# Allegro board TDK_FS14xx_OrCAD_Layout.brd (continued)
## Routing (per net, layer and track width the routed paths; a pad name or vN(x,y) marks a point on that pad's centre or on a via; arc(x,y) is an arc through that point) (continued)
LED3: length 19.7
  TOP w0.229: U11.14 249.07,76.2 249.78,75.49 249.78,75.46 v2(251.21,74.04) 251.84,73.41 D3.1
  BOTTOM w0.305: U10.19 240.79,75.87 241.99,74.68 243.21,74.68 243.57,75.04 250.2,75.04 v2(251.21,74.04)
LED4: length 18.4
  TOP w0.229: D4.1 251.46,75.31 v2(251.21,75.56) 250.17,76.6 U11.15
  BOTTOM w0.305: U10.18 241.66,76.53 241.96,76.23 243.15,76.23 243.46,75.92 250.85,75.92 v2(251.21,75.56)
LED5: length 18.2
  TOP w0.229: U11.16 251.12,77 v2(251.21,77.09)
  TOP w0.305: D5.1 251.33,77.22 v2(251.21,77.09)
  BOTTOM w0.305: U10.17 240.93,77.18 241.48,77.72 243.36,77.72 244.4,76.68 250.8,76.68 v2(251.21,77.09)
LED6: length 19.1
  TOP w0.229: U11.17 249.99,77.4 v2(251.21,78.61)
  TOP w0.305: v2(251.21,78.61) 251.71,79.12 D6.1
  BOTTOM w0.305: v2(251.21,78.61) 250.57,79.25 241.76,79.25 241.3,78.79 241.3,78.36 240.77,77.83 U10.16
LED7: length 21.5
  TOP w0.229: v2(251.21,80.14) 250.62,79.55 248.62,79.55 247.41,78.35 U11.18
  TOP w0.305: v2(251.21,80.14) 252.09,81.03 D7.1
  BOTTOM w0.305: U10.15 240.25,78.48 241.27,79.5 241.27,80.31 241.73,80.77 250.57,80.77 v2(251.21,80.14)
LED8: length 23.8
  TOP w0.229: v2(251.21,81.66) 249.61,80.06 248.39,80.06 247.01,78.69 U11.19
  TOP w0.305: D8.1 252.48,82.93 v2(251.21,81.66)
  BOTTOM w0.305: U10.14 240.14,79.13 240.59,79.58 240.59,81.2 241.81,82.42 250.44,82.42 v2(251.21,81.66)
Net_107: length 1.2
  TOP w0.305: 200.6,52.97 200.6,53.71 v3(200.28,54.03)
Net_108: length 1.2
  TOP w0.305: 205.8,99.43 205.8,98.69 v3(206.12,98.37)
OPT: length 69.8
  TOP w0.305: R77.2 R76.1 271.59,32.57 271.3,32.87 267.82,32.87 J21.1 J20.2
  L3 w0.305: J13.6 273.08,82.55 273.86,81.76 273.86,38.91 J21.1
PGOOD1: length 244.5
  TOP w0.229: U11.10 247.41,74.13 244.14,70.87 v2(242.32,70.87)
  TOP w0.305: v2(242.32,70.87) 239.62,73.56 233.39,73.56 v2(230.7,70.87) ; v2(54.76,99.75) 53.87,100.63 53.01,100.63 52.87,100.77 U1.2
  L3 w0.305: v2(242.32,70.87) 245.14,68.05 263.42,68.05 J13.19 ; v2(230.7,70.87) 229.96,71.6 226.21,71.6 218.72,79.1 81,79.1 62.72,97.38 57.12,97.38 v2(54.76,99.75)
  BOTTOM w0.305: U10.3 232.37,73.92 232.03,73.58 232.03,72.19 v2(230.7,70.87) R56.1
PGOOD2: length 195.3
  TOP w0.229: v2(242.32,72.39) 245.01,72.39 247.01,74.4 U11.9
  TOP w0.305: v2(230.7,72.39) 232.45,74.14 240.56,74.14 v2(242.32,72.39) ; v2(105.38,100.05) 104.78,100.66 103.78,100.66 103.67,100.77 U2.2
  L3 w0.305: v2(105.38,100.05) 105.38,99.92 107.54,97.76 123.65,97.76 137.24,84.18 227.97,84.18 228.73,83.41 228.73,74.36 v2(230.7,72.39) ; v2(242.32,72.39) 245.87,68.83 265.18,68.83 J13.17
  BOTTOM w0.305: R57.1 v2(230.7,72.39) 231.44,73.13 231.44,73.81 232.21,74.57 U10.4
PGOOD3: length 140.9
  TOP w0.229: v2(242.32,73.91) 245.82,73.91 246.62,74.71 U11.8
  TOP w0.305: v2(242.32,73.91) 241.45,74.78 231.56,74.78 v2(230.7,73.91) ; v2(156.36,99.75) 155.4,100.71 154.53,100.71 154.47,100.77 U3.2
  L3 w0.305: v2(230.7,73.91) 229.31,75.3 229.31,84.86 225.5,88.67 184.15,88.67 175.23,97.59 158.52,97.59 v2(156.36,99.75) ; J13.15 265.81,70.74 255.22,70.74 254.2,71.75 244.47,71.75 v2(242.32,73.91)
  BOTTOM w0.305: R58.2 v2(230.7,73.91) 232.01,75.22 U10.5
PGOOD4: length 246.3
  TOP w0.229: U11.7 242.75,75 v2(242.32,75.44)
  TOP w0.305: U4.2 48.73,51.63 48.51,51.84 47.75,51.84 47.45,52.15 v2(47.45,52.63) ; v2(230.7,75.44) v2(242.32,75.44)
  L3 w0.305: v2(242.32,75.44) 244.45,73.3 253.24,73.3 254.03,72.52 266.57,72.52 J13.13 ; v2(47.45,52.63) 47.47,52.63 66.14,71.3 213.13,71.3 215.42,69.01 230.2,69.01 231.57,70.38 231.57,74.33 v2(230.7,75.44)
  BOTTOM w0.305: R59.1 v2(230.7,75.44) 231.14,75.87 U10.6
PGOOD5: length 198.6
  TOP w0.229: v2(242.32,76.96) 243.88,75.4 U11.6
  TOP w0.305: U5.2 99.53,51.63 99.26,51.89 98.5,51.89 98.25,52.15 v2(98.25,52.63) ; v2(230.7,76.96) v2(242.32,76.96)
  L3 w0.305: v2(242.32,76.96) 242.95,76.33 265.56,76.33 J13.9 ; v2(230.7,76.96) 232,76.96 232.56,76.4 232.56,69.24 228.98,65.66 210.13,65.66 209.32,66.47 112.17,66.47 98.32,52.63 v2(98.25,52.63)
  BOTTOM w0.305: R60.1 v2(230.7,76.96) 231.14,76.53 U10.7
PGOOD6: length 157
  TOP w0.229: v2(242.32,78.49) 243.31,77.5 243.31,77.24 244.75,75.8 U11.5
  TOP w0.305: U6.2 150.33,51.63 150.11,51.84 149.35,51.84 149.05,52.15 v2(149.05,52.63) ; v2(230.7,78.49) v2(242.32,78.49)
  L3 w0.305: v2(230.7,78.49) 233.71,78.49 235.71,76.48 235.71,66.62 230.66,61.57 207.92,61.57 207.52,61.98 158.47,61.98 149.12,52.63 v2(149.05,52.63) ; J13.7 252.78,80.01 252.17,79.4 243.23,79.4 v2(242.32,78.49)
  BOTTOM w0.305: U10.8 232.01,77.18 v2(230.7,78.49) R61.1
PGOOD7: length 107.7
  TOP w0.229: v2(242.32,80.01) 244.09,78.23 244.09,77.24 245.14,76.2 U11.4
  TOP w0.305: v2(195.53,103.12) 196.32,103.91 199.2,103.91 199.34,103.77 U7.9 ; v2(230.7,80.01) 231.28,80.59 241.73,80.59 v2(242.32,80.01)
  L3 w0.305: v2(195.53,103.12) 193.98,101.57 193.98,96.57 197.66,92.89 223.16,92.89 229.9,86.16 229.9,80.82 v2(230.7,80.01) ; J13.5 266.12,81.97 253.21,81.97 252.17,80.92 243.23,80.92 v2(242.32,80.01)
  BOTTOM w0.305: R62.2 v2(230.7,80.01) 231.47,79.24 231.47,78.61 232.26,77.83 U10.9
PGOOD8: length 117
  TOP w0.229: v2(242.32,81.53) 244.91,78.94 244.91,77.17 245.47,76.6 U11.3
  TOP w0.305: U8.9 206.77,48.63 207.14,48.26 v2(209.63,48.26) ; v2(230.7,81.53) v2(242.32,81.53)
  L3 w0.305: v2(242.32,81.53) 244.55,83.77 265.38,83.77 J13.3 ; v2(230.7,81.53) 231.34,80.9 235.28,80.9 237.24,78.94 238.68,78.94 239.73,77.9 239.73,66.09 232.18,58.55 215.34,58.55 212.39,55.6 v2(212.39,53.98)
  BOTTOM w0.305: R63.1 v2(230.7,81.53) 232.03,80.21 232.03,78.82 232.37,78.48 U10.10 ; v2(209.63,48.26) 210.36,48.26 212.39,50.29 v2(212.39,53.98)
SALERT7: length 13.5
  TOP w0.305: U7.14 198.45,100.15 197.84,99.54 191.24,99.54 J17.2
  BOTTOM w0.305: J17.2 190.12,98.42 R31.1
SALERT8: length 19.2
  TOP w0.305: U8.14 206.3,52.25 206.4,52.35 209.63,52.35 209.88,52.6 211.46,52.6 212.09,51.97 212.09,47.88 J14.2
  BOTTOM w0.305: R46.1 216.66,43.81 J14.2
SCL: length 492.5
  TOP w0.305: v2(194.87,100.36) 197.82,100.36 198.34,100.88 U7.13 ; U8.13 209.28,51.52 v2(209.32,51.56) ; v2(55.68,101.6) 53.54,101.6 53.27,101.87 U1.4 ; v2(106.55,101.6) 104.39,101.6 104.12,101.87 U2.4 ; J11.1 R48.1 ; v2(157.33,101.63) 155.14,101.63 154.89,101.87 U3.4 ; v2(94.59,50.16) 95.28,50.85 98.76,50.85 99.08,50.53 U5.4 ; U4.4 48.28,50.53 47.96,50.85 44.48,50.85 v2(43.79,50.16) ; v2(145.39,50.16) 146.08,50.85 149.56,50.85 149.88,50.53 U6.4
  L3 w0.305: v2(209.32,51.56) 211.12,49.76 224.84,49.76 239.88,34.72 245.49,34.72 264.46,15.75 J11.1 ; v2(198.3,77.09) v2(162.79,77.09) 162.74,77.14 v2(111.99,77.14) v2(60.63,77.14)
  BOTTOM w0.305: v2(55.68,101.6) 57.66,101.6 60.63,98.63 v2(60.63,77.14) 60.63,75.03 43.79,58.19 v2(43.79,50.16) ; v2(194.87,100.36) 193.68,99.16 193.68,81.71 v2(198.3,77.09) 209.32,66.07 v2(209.32,51.56) ; v2(157.33,101.63) 162.79,96.16 v2(162.79,77.09) 162.79,74.63 145.39,57.23 v2(145.39,50.16) ; v2(106.55,101.6) 111.99,96.16 v2(111.99,77.14) 111.99,75.06 94.59,57.66 v2(94.59,50.16)
SDA: length 483.7
  TOP w0.305: v2(155.09,99.77) 154.64,100.23 U3.1 ; U5.1 99.79,52.17 v2(99.36,52.6) ; v2(104.19,99.75) 103.71,100.23 U2.1 ; v2(210.97,51.59) 210.19,50.8 U8.12 ; J11.2 R47.1 ; v2(48.56,52.6) 48.99,52.17 U4.1 ; v2(150.16,52.6) 150.59,52.17 U6.1 ; v2(196.49,101.24) 196.85,101.6 U7.12 ; v2(53.34,99.75) 52.86,100.23 U1.1
  L3 w0.305: v2(144.07,52.6) 146.91,52.6 147.68,51.84 149.4,51.84 v2(150.16,52.6) ; v2(99.36,52.6) 98.6,51.84 96.88,51.84 96.11,52.6 v2(93.27,52.6) ; v2(42.47,52.6) 45.31,52.6 46.08,51.84 47.8,51.84 v2(48.56,52.6) ; v2(204.57,75.26) v2(158.27,75.26) v2(108.64,75.26) v2(57.58,75.26) ; v2(210.97,51.59) 226.06,51.59 237.26,40.39 246.38,40.39 J11.2
  BOTTOM w0.305: v2(93.27,52.6) 93.27,59.77 108.64,75.13 v2(108.64,75.26) 108.66,75.29 108.66,96.55 105.99,99.21 104.72,99.21 v2(104.19,99.75) ; v2(155.09,99.77) 155.85,99.01 157,99.01 158.27,97.74 v2(158.27,75.26) 144.07,61.06 v2(144.07,52.6) ; v2(196.49,101.24) 196.49,83.36 204.57,75.29 v2(204.57,75.26) 204.6,75.26 210.97,68.88 v2(210.97,51.59) ; v2(42.47,52.6) 42.47,60.15 v2(57.58,75.26) 57.58,99.39 56.26,100.71 54.31,100.71 v2(53.34,99.75)
SYNC7: length 13.4
  TOP w0.305: J17.1 191.48,102.32 U7.11
  BOTTOM w0.305: J17.1 190.12,100.97 R54.1
SYNC8: length 18.2
  TOP w0.305: U8.11 206.87,50.08 206.91,50.04 210.03,50.04 211.28,48.79 211.28,46.15 J14.1
  BOTTOM w0.305: J14.1 216.66,41.27 R38.1
VOUT1: length 112.7
  TOP w0.305: U1.5 53.73,102.43 v2(53.87,102.29)
  TOP w0.508: J2.1 50,139.23 C102.2
  TOP w0.813: 37.89,141.68 T3.1 ; T3.1 40.93,144.73 ; T3.1 37.89,144.73 ; T3.1 40.93,141.68 ; 42.89,134.67 T3.3 ; T3.3 45.93,137.72 ; T3.3 42.89,137.72 ; T3.3 45.93,134.67 ; T3.2 40.93,134.67 ; T3.2 40.93,137.72 ; T3.2 37.89,134.67 ; T3.2 37.89,137.72 ; T3.4 45.93,141.68 ; T3.4 42.89,141.68 ; T3.4 42.89,144.73 ; T3.4 45.93,144.73
  L3 w0.305: v2(51.41,106.91) 51.41,135.25 49.53,137.13 J2.1 ; v2(51.41,106.02) 51.41,104.75 v2(53.87,102.29)
  BOTTOM w0.813: T3.1 40.93,144.73 ; T3.1 37.89,144.73 ; T3.1 40.93,141.68 ; T3.1 37.89,141.68 ; 37.89,137.72 T3.2 ; T3.2 37.89,134.67 ; T3.2 40.93,137.72 ; T3.2 40.93,134.67 ; T3.3 45.93,134.67 ; T3.3 45.93,137.72 ; T3.3 42.89,137.72 ; T3.3 42.89,134.67 ; 42.89,144.73 T3.4 ; T3.4 45.93,144.73 ; T3.4 45.93,141.68 ; T3.4 42.89,141.68
  vias: v1(50.27,102.92) v1(50.8,102.93) v1(51.33,102.92) v2(49.38,106.91) v2(49.38,106.02) v2(50.39,106.91) v2(50.39,106.02)
VOUT2: length 112.7
  TOP w0.305: v2(104.67,102.29) 104.53,102.43 U2.5
  TOP w0.635: C103.2 100.8,139.23 J3.1
  TOP w0.813: 88.69,137.72 T5.2 ; T5.2 91.73,137.72 ; T5.2 88.69,134.67 ; T5.2 91.73,134.67 ; T5.3 96.73,137.72 ; T5.3 96.73,134.67 ; T5.3 93.69,137.72 ; T5.3 93.69,134.67 ; T5.4 96.73,144.73 ; T5.4 96.73,141.68 ; T5.4 93.69,141.68 ; T5.4 93.69,144.73 ; 88.69,141.68 T5.1 ; T5.1 91.73,144.73 ; T5.1 91.73,141.68 ; T5.1 88.69,144.73
  L3 w0.305: v2(104.67,102.29) 102.21,104.75 v2(102.21,106.02) ; J3.1 100.33,137.36 102.21,135.48 v2(102.21,106.91)
  BOTTOM w0.813: T5.1 91.73,141.68 ; T5.1 91.73,144.73 ; T5.1 88.69,141.68 ; T5.1 88.69,144.73 ; 93.69,137.72 T5.3 ; T5.3 96.73,137.72 ; T5.3 93.69,134.67 ; T5.3 96.73,134.67 ; T5.2 91.73,134.67 ; T5.2 91.73,137.72 ; T5.2 88.69,137.72 ; T5.2 88.69,134.67 ; T5.4 96.73,141.68 ; T5.4 93.69,144.73 ; T5.4 93.69,141.68 ; T5.4 96.73,144.73
  vias: v1(101.07,102.92) v1(101.6,102.93) v1(102.13,102.92) v2(100.18,106.91) v2(100.18,106.02) v2(101.19,106.91) v2(101.19,106.02)
VOUT3: length 112.7
  TOP w0.305: v2(155.47,102.29) 155.33,102.43 U3.5
  TOP w0.508: J4.1 151.6,139.23 C104.2
  TOP w0.813: T7.2 142.53,137.72 ; T7.2 139.49,134.67 ; T7.2 142.53,134.67 ; T7.2 139.49,137.72 ; 144.49,144.73 T7.4 ; T7.4 147.53,144.73 ; T7.4 147.53,141.68 ; T7.4 144.49,141.68 ; T7.3 147.53,137.72 ; T7.3 147.53,134.67 ; T7.3 144.49,137.72 ; T7.3 144.49,134.67 ; T7.1 142.53,141.68 ; T7.1 142.53,144.73 ; T7.1 139.49,144.73 ; T7.1 139.49,141.68
  L3 w0.305: v2(155.47,102.29) 153.01,104.75 v2(153.01,106.02) ; v2(153.01,106.91) 153.01,135.69 151.13,137.57 J4.1
  BOTTOM w0.813: 144.49,134.67 T7.3 ; T7.3 147.53,134.67 ; T7.3 144.49,137.72 ; T7.3 147.53,137.72 ; 139.49,137.72 T7.2 ; T7.2 142.53,134.67 ; T7.2 142.53,137.72 ; T7.2 139.49,134.67 ; 139.49,141.68 T7.1 ; T7.1 142.53,144.73 ; T7.1 142.53,141.68 ; T7.1 139.49,144.73 ; 144.49,141.68 T7.4 ; T7.4 147.53,141.68 ; T7.4 144.49,144.73 ; T7.4 147.53,144.73
  vias: v1(151.87,102.92) v1(152.4,102.93) v1(152.93,102.92) v2(150.98,106.91) v2(150.98,106.02) v2(151.99,106.91) v2(151.99,106.02)
VOUT4: length 112.2
  TOP w0.305: v2(47.73,50.11) 47.87,49.97 U4.5
  TOP w0.635: J5.1 49.53,15.79 C106.2
  TOP w0.813: 42.89,14.68 T9.4 ; T9.4 42.89,17.73 ; T9.4 45.93,17.73 ; T9.4 45.93,14.68 ; T9.2 40.93,7.67 ; T9.2 37.89,7.67 ; T9.2 40.93,10.72 ; T9.2 37.89,10.72 ; T9.1 40.93,17.73 ; T9.1 37.89,17.73 ; T9.1 40.93,14.68 ; T9.1 37.89,14.68 ; T9.3 45.93,10.72 ; T9.3 42.89,7.67 ; T9.3 42.89,10.72 ; T9.3 45.93,7.67
  L3 w0.305: v2(50.19,45.49) 50.19,16.13 49.53,15.47 J5.1 ; v2(47.73,50.11) 50.19,47.65 v2(50.19,46.38)
  BOTTOM w0.813: T9.3 45.93,10.72 ; T9.3 45.93,7.67 ; T9.3 42.89,7.67 ; T9.3 42.89,10.72 ; 37.89,10.72 T9.2 ; T9.2 37.89,7.67 ; T9.2 40.93,7.67 ; T9.2 40.93,10.72 ; 37.89,17.73 T9.1 ; T9.1 40.93,14.68 ; T9.1 37.89,14.68 ; T9.1 40.93,17.73 ; T9.4 45.93,17.73 ; T9.4 42.89,14.68 ; T9.4 45.93,14.68 ; T9.4 42.89,17.73
  vias: v1(50.27,49.48) v1(50.8,49.47) v1(51.33,49.48) v2(51.21,46.38) v2(51.21,45.49) v2(52.22,46.38) v2(52.22,45.49)
VOUT5: length 112.2
  TOP w0.305: v2(98.53,50.11) 98.67,49.97 U5.5
  TOP w0.508: J6.1 100.8,13.17 C105.2
  TOP w0.813: T11.3 96.73,7.67 ; T11.3 96.73,10.72 ; T11.3 93.69,7.67 ; T11.3 93.69,10.72 ; 93.69,14.68 T11.4 ; T11.4 96.73,14.68 ; T11.4 96.73,17.73 ; T11.4 93.69,17.73 ; T11.1 91.73,17.73 ; T11.1 91.73,14.68 ; T11.1 88.69,17.73 ; T11.1 88.69,14.68 ; 88.69,10.72 T11.2 ; T11.2 88.69,7.67 ; T11.2 91.73,7.67 ; T11.2 91.73,10.72
  L3 w0.305: v2(98.53,50.11) 100.99,47.65 v2(100.99,46.38) ; v2(100.99,45.49) 100.99,16.36 100.33,15.7 J6.1
  BOTTOM w0.813: 88.69,14.68 T11.1 ; T11.1 88.69,17.73 ; T11.1 91.73,14.68 ; T11.1 91.73,17.73 ; 93.69,7.67 T11.3 ; T11.3 96.73,10.72 ; T11.3 93.69,10.72 ; T11.3 96.73,7.67 ; T11.4 96.73,17.73 ; T11.4 96.73,14.68 ; T11.4 93.69,14.68 ; T11.4 93.69,17.73 ; T11.2 91.73,10.72 ; T11.2 91.73,7.67 ; T11.2 88.69,7.67 ; T11.2 88.69,10.72
  vias: v1(101.07,49.48) v1(101.6,49.47) v1(102.13,49.48) v2(102.01,46.38) v2(102.01,45.49) v2(103.02,46.38) v2(103.02,45.49)
VOUT6: length 112.2
  TOP w0.305: v2(149.33,50.11) 149.47,49.97 U6.5
  TOP w0.508: J7.1 151.6,13.17 C107.2
  TOP w0.813: 144.49,14.68 T13.4 ; T13.4 144.49,17.73 ; T13.4 147.53,17.73 ; T13.4 147.53,14.68 ; 139.49,14.68 T13.1 ; T13.1 142.53,17.73 ; T13.1 142.53,14.68 ; T13.1 139.49,17.73 ; T13.3 147.53,10.72 ; T13.3 144.49,10.72 ; T13.3 144.49,7.67 ; T13.3 147.53,7.67 ; 139.49,7.67 T13.2 ; T13.2 142.53,10.72 ; T13.2 142.53,7.67 ; T13.2 139.49,10.72
  L3 w0.305: J7.1 151.13,15.7 151.79,16.36 v2(151.79,45.49) ; v2(149.33,50.11) 151.79,47.65 v2(151.79,46.38)
  BOTTOM w0.813: T13.3 147.53,10.72 ; T13.3 147.53,7.67 ; T13.3 144.49,10.72 ; T13.3 144.49,7.67 ; T13.1 142.53,17.73 ; T13.1 142.53,14.68 ; T13.1 139.49,14.68 ; T13.1 139.49,17.73 ; T13.4 147.53,14.68 ; T13.4 144.49,14.68 ; T13.4 147.53,17.73 ; T13.4 144.49,17.73 ; T13.2 142.53,10.72 ; T13.2 139.49,10.72 ; T13.2 142.53,7.67 ; T13.2 139.49,7.67
  vias: v1(151.87,49.48) v1(152.4,49.47) v1(152.93,49.48) v2(152.81,46.38) v2(152.81,45.49) v2(153.82,46.38) v2(153.82,45.49)
VOUT7: length 110.4
  TOP w0.508: C108.2 204,139.23 J9.1
  TOP w0.813: T15.1 211.11,141.68 ; T15.1 208.07,141.68 ; T15.1 208.07,144.73 ; T15.1 211.11,144.73 ; 213.07,144.73 T15.4 ; T15.4 216.11,144.73 ; T15.4 213.07,141.68 ; T15.4 216.11,141.68 ; T15.3 216.11,137.72 ; T15.3 216.11,134.67 ; T15.3 213.07,134.67 ; T15.3 213.07,137.72 ; T15.2 211.11,137.72 ; T15.2 208.07,134.67 ; T15.2 208.07,137.72 ; T15.2 211.11,134.67
  L3 w0.305: v2(204.34,106.27) 204.37,106.3 204.9,106.3 ; J9.1 205.41,138.76 205.41,106.81 204.9,106.3 ; 204.9,106.3 v2(206.35,106.3)
  BOTTOM w0.305: v2(206.35,106.3) R42.1 C51.1
  BOTTOM w0.813: T15.1 211.11,144.73 ; T15.1 208.07,144.73 ; T15.1 211.11,141.68 ; T15.1 208.07,141.68 ; T15.2 211.11,134.67 ; T15.2 211.11,137.72 ; T15.2 208.07,134.67 ; T15.2 208.07,137.72 ; 213.07,141.68 T15.4 ; T15.4 216.11,141.68 ; T15.4 216.11,144.73 ; T15.4 213.07,144.73 ; 213.07,134.67 T15.3 ; T15.3 213.07,137.72 ; T15.3 216.11,137.72 ; T15.3 216.11,134.67
  vias: v1(201.8,103.78) v1(202.03,103.45) v1(202.26,103.78) v1(202.49,103.45) v1(202.72,103.78) v1(202.95,103.45) v1(203.17,103.78) v1(203.4,103.45) v1(203.63,103.78) v1(203.86,103.45) v1(204.09,103.78) v1(204.32,103.45) v1(204.55,103.78) v1(204.77,103.45) v2(203.45,109.83) v2(203.45,108.94) v2(203.45,108.05) v2(203.45,107.16) v2(203.45,106.27) v2(203.45,105.38) v2(204.34,109.83) v2(204.34,108.94) v2(204.34,108.05) v2(204.34,107.16) v2(204.34,105.38)
VOUT8: length 110.5
  TOP w0.508: C109.2 202.4,13.17 J8.1
  TOP w0.813: T17.2 193.33,7.67 ; T17.2 190.29,7.67 ; T17.2 193.33,10.72 ; T17.2 190.29,10.72 ; T17.1 193.33,14.68 ; T17.1 190.29,14.68 ; T17.1 193.33,17.73 ; T17.1 190.29,17.73 ; 195.29,17.73 T17.4 ; T17.4 198.33,17.73 ; T17.4 195.29,14.68 ; T17.4 198.33,14.68 ; T17.3 198.33,10.72 ; T17.3 195.29,7.67 ; T17.3 198.33,7.67 ; T17.3 195.29,10.72
  L3 w0.305: J8.1 201.29,13.34 201.29,45.01 v2(200.2,46.1) 202.03,46.1 v2(202.06,46.13)
  BOTTOM w0.305: v2(200.2,46.1) R52.1 C121.1
  BOTTOM w0.813: 190.29,7.67 T17.2 ; T17.2 193.33,10.72 ; T17.2 190.29,10.72 ; T17.2 193.33,7.67 ; 190.29,14.68 T17.1 ; T17.1 193.33,14.68 ; T17.1 190.29,17.73 ; T17.1 193.33,17.73 ; T17.3 198.33,10.72 ; T17.3 195.29,10.72 ; T17.3 195.29,7.67 ; T17.3 198.33,7.67 ; 195.29,17.73 T17.4 ; T17.4 198.33,14.68 ; T17.4 195.29,14.68 ; T17.4 198.33,17.73
  vias: v1(201.63,48.95) v1(201.85,48.62) v1(202.08,48.95) v1(202.31,48.62) v1(202.54,48.95) v1(202.77,48.62) v1(203,48.95) v1(203.23,48.62) v1(203.45,48.95) v1(203.68,48.62) v1(203.91,48.95) v1(204.14,48.62) v1(204.37,48.95) v1(204.6,48.62) v2(202.06,47.02) v2(202.06,45.24) v2(202.06,44.35) v2(202.06,43.46) v2(202.06,42.57) v2(202.95,47.02) v2(202.95,46.13) v2(202.95,45.24) v2(202.95,44.35) v2(202.95,43.46) v2(202.95,42.57)
N106541: length 3.6
  TOP w0.305: C9.2 98.59,100.89 v1(99.14,100.89) 99.57,101.33 U2.11
  BOTTOM w0.305: R4.1 99.12,100.87 v1(99.14,100.89)
N109036: length 1.9
  TOP w0.305: U2.10 v1(99.06,101.87)
  BOTTOM w0.305: v1(99.06,101.87) 99.28,101.66 C132.2
N111800: length 3.6
  TOP w0.305: U3.11 150.37,101.33 v1(149.94,100.89) 149.39,100.89 C15.2
  BOTTOM w0.305: v1(149.94,100.89) 149.92,100.87 R7.1
N112773: length 3.6
  TOP w0.305: C3.2 47.79,100.89 v1(48.34,100.89) 48.77,101.33 U1.11
  BOTTOM w0.305: R1.1 48.32,100.87 v1(48.34,100.89)
N113813: length 3.6
  TOP w0.305: C21.2 53.81,51.51 v1(53.26,51.51) 52.83,51.07 U4.11
  BOTTOM w0.305: v1(53.26,51.51) 53.28,51.53 R10.1
N124020: length 1
  TOP w0.305: R6.2 103.54,102.97 U2.6
N125365: length 1
  TOP w0.305: R3.2 52.74,102.97 U1.6
N125599: length 1
  TOP w0.305: R12.2 48.86,49.43 U4.6
N125833: length 1
  TOP w0.305: U3.6 154.34,102.97 R9.2
N143732: length 3.6
  TOP w0.305: C29.2 104.61,51.51 v1(104.06,51.51) 103.63,51.07 U5.11
  BOTTOM w0.305: v1(104.06,51.51) 104.08,51.53 R21.1
N143740: length 3.6
  TOP w0.305: U6.11 154.43,51.07 v1(154.86,51.51) 155.41,51.51 C30.2
  BOTTOM w0.305: v1(154.86,51.51) 154.88,51.53 R22.1
N143880: length 1
  TOP w0.305: R23.2 99.66,49.43 U5.6
N143888: length 1
  TOP w0.305: R24.2 150.46,49.43 U6.6
N983153:
  vias: v1(203,99.19) v1(203.17,99.39) v1(203.4,99.19)
N983255:
  vias: v1(198.63,99.16) v1(198.63,98.65) v1(198.63,98.15) v1(199.14,99.16) v1(199.14,98.65) v1(199.14,98.15)
N983335: length 3.9
  TOP w0.305: R27.2 207.59,98.66 C43.2 207.61,98.82 206.28,100.15 U7.2
N983701: length 3.2
  TOP w0.305: v2(207.32,100.9) C45.2 U7.4
  BOTTOM w0.305: v2(207.32,100.9) 206.76,100.9 R36.2
N983781: length 4.5
  TOP w0.305: U7.5 207.63,102.32 207.77,102.46 v2(207.77,102.51) C44.2
  BOTTOM w0.305: R36.1 206.72,102.05 207.01,102.34 207.59,102.34 v2(207.77,102.51)
N983905: length 2.1
  TOP w0.305: R39.1 199.97,103.12 200.05,103.05 U7.10
N983923: length 6.4
  TOP w0.305: U7.6 206.68,103.05 v2(206.74,103.11)
  BOTTOM w0.305: R42.2 C51.2 208.49,105.28 208.69,105.08 208.69,103.66 208.47,103.44 R44.2 207.07,103.44 v2(206.74,103.11)
N1133327:
  vias: v1(203,53.21) v1(203.23,53.01) v1(203.4,53.21)
N1133411:
  vias: v1(207.26,54.25) v1(207.26,53.75) v1(207.26,53.24) v1(207.77,54.25) v1(207.77,53.75) v1(207.77,53.24)
N1133439: length 3.9
  TOP w0.305: R45.2 198.81,53.74 C115.2 198.79,53.58 200.12,52.25 U8.2
N1133683: length 3.2
  TOP w0.305: v2(199.08,51.5) C116.2 U8.4
  BOTTOM w0.305: R50.2 199.64,51.5 v2(199.08,51.5)
N1133735: length 4.5
  TOP w0.305: C117.2 v2(198.63,49.89) 198.63,49.94 198.77,50.08 U8.5
  BOTTOM w0.305: R50.1 199.61,50.06 198.81,50.06 v2(198.63,49.89)
N1133791: length 2.1
  TOP w0.305: U8.10 206.35,49.35 206.43,49.28 R51.1
N1133799: length 6.5
  TOP w0.305: U8.6 199.72,49.35 v2(199.66,49.29)
  BOTTOM w0.305: v2(199.66,49.29) 199.33,48.96 R53.2 197.86,48.96 197.64,48.75 197.64,47.34 197.86,47.12 C121.2 R52.2
N1144589: length 53.4
  TOP w0.305: SW3.10 275.64,99.57 ; 275.64,99.57 275.95,99.26 275.95,97.28 275.69,97.03 SW3.9 ; 275.64,99.57 275.82,99.75 275.82,101.68 275.39,102.11 ; 275.34,104.65 275.84,104.14 275.84,102.57 275.39,102.11 ; 275.34,104.65 SW3.12 ; 275.34,104.65 275.84,105.16 275.84,106.76 275.41,107.19 ; SW3.15 275.51,112.27 ; 275.51,112.27 275.84,111.94 275.84,110.34 275.23,109.73 ; 275.51,112.27 275.69,112.45 275.69,114.25 275.13,114.81 SW3.16 272.95,114.81 269.62,118.14 269.62,128.78 SW1.2 ; 275.39,102.11 SW3.11 ; SW3.13 275.41,107.19 ; 275.41,107.19 275.82,107.59 275.82,109.14 275.23,109.73 ; SW3.14 275.23,109.73
N1166950: length 4.7
  TOP w0.305: R75.1 267.08,52.7 267.33,52.96
N1167645: length 4.7
  TOP w0.305: R55.1 262.96,43.56 SW2.1
N1170426: length 3.8
  BOTTOM w0.305: R64.1 234.95,72.82 234.5,73.27 U10.2
N1170926: length 1.9
  TOP w0.305: D4.2 R69.2
N1170982: length 1.9
  TOP w0.305: D5.2 R70.2
N1171050: length 1.9
  TOP w0.305: D6.2 R71.2
N1171118: length 1.9
  TOP w0.305: D7.2 R72.2
N1171178: length 1.9
  TOP w0.305: R73.2 D8.2
N1171210: length 5.5
  BOTTOM w0.305: R65.2 236.22,73.19 236.96,73.92 U10.22
N1176310: length 1.9
  TOP w0.305: D3.2 R68.2
N1183669: length 1.9
  TOP w0.305: D1.2 R66.2
N1183969: length 1.9
  TOP w0.305: D2.2 R67.2
N1197737: length 5.3
  TOP w0.305: R74.1 SW1.1
N1197747: length 5.3
  TOP w0.305: R18.1 SW1.3
N1234759: length 1.9
  TOP w0.305: U1.10 v1(48.26,101.87)
  BOTTOM w0.305: C134.2 48.48,101.66 v1(48.26,101.87)
N1235035: length 1.9
  TOP w0.305: U4.10 v1(53.34,50.53)
  BOTTOM w0.305: v1(53.34,50.53) 53.12,50.74 C135.2
N1235784: length 1.9
  TOP w0.305: U6.10 v1(154.94,50.53)
  BOTTOM w0.305: v1(154.94,50.53) 154.72,50.74 C136.2
N1236304: length 1.9
  TOP w0.305: U5.10 v1(104.14,50.53)
  BOTTOM w0.305: v1(104.14,50.53) 103.92,50.74 C137.2
N1413705: length 6.5
  TOP w0.305: J19.2 J20.1 R78.2 R77.1

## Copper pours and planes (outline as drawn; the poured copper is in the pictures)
3.3V on TOP: 267.92,89.92 267.92,85.5 265.1,85.5 265.1,55.68 260.88,55.68 260.88,45.21 262.1,45.21 262.1,27.3 271.27,27.3 271.27,28.98 272.72,28.98 272.72,23.29 257.07,23.29 256.97,23.39 256.97,45.44 256.95,45.47 241.35,45.47 241.35,60.15 224.54,60.15 224.54,83.64 243.59,83.64 246.94,80.29 246.94,78.77 246.15,77.98 245.41,77.98 245.29,78.11 245.29,79.55 243.03,81.81 229.51,81.81 229.51,70 231.29,70 234.29,73 238.56,73 243.15,68.4 259.49,68.4 259.49,89.92
3.3V on BOTTOM: 239.78,53.16 244.53,53.16 244.53,46.05 240.97,46.05 240.97,51.03 239.78,51.03
AGND1 on BOTTOM: 205.18,102.11 205.18,102.67 203.2,102.67 203.2,102.11
AGND1 on L2: 203.12,102.95 203.12,102.03 205.21,102.03 205.21,102.95
AGND1 on L3: 203.12,102.03 205.94,102.03 207.44,103.53 211.66,103.53 211.76,103.63 211.76,111.23 184.58,111.23 184.56,111.2 184.56,96.7 187.38,93.88 192.63,93.88 192.63,102.82 193.73,103.91 196.24,103.91 196.24,102.62 197.61,102.62 197.61,103.45 202.97,103.45 203.12,103.3
AGND2 on BOTTOM: 201.22,50.29 201.22,49.73 203.2,49.73 203.2,50.29
AGND2 on L2: 201.32,49.45 203.33,49.45 203.33,50.42 201.32,50.42
AGND2 on L3: 203.28,50.37 200.46,50.37 198.96,48.87 194.74,48.87 194.64,48.77 194.64,41.17 209.12,41.17 210.13,40.16 221.21,40.16 221.46,40.41 221.46,46.3 219.84,47.93 211.84,47.93 209.88,49.89 206.63,49.89 205.69,48.95 203.43,48.95 203.28,49.1
PGND on TOP (solid shape): 51.07,50.75 51.67,50.75 51.67,49.95 49.93,49.95 49.93,51.75 51.07,51.75
PGND on TOP (solid shape): 51.67,100.65 50.53,100.65 50.53,101.65 49.93,101.65 49.93,102.45 51.67,102.45
PGND on TOP (solid shape): 101.87,50.75 102.47,50.75 102.47,49.95 100.73,49.95 100.73,51.75 101.87,51.75
PGND on TOP (solid shape): 102.47,100.65 101.33,100.65 101.33,101.65 100.73,101.65 100.73,102.45 102.47,102.45
PGND on TOP (solid shape): 152.67,50.75 153.27,50.75 153.27,49.95 151.53,49.95 151.53,51.75 152.67,51.75
PGND on TOP (solid shape): 153.27,100.65 152.13,100.65 152.13,101.65 151.53,101.65 151.53,102.45 153.27,102.45
PGND on TOP (solid shape): outline of 651 points within 101.96,93.07 151.28,151.08
PGND on TOP (solid shape): outline of 1438 points within 1.37,1.3 49.68,151.05
PGND on TOP: 276.63,70.92 278.08,70.92 278.08,1.32 203.61,1.32 203.61,24 205.69,24 205.69,47.47 209.14,47.47 209.14,55.12 206.86,55.12 205.03,53.29 205.03,49.5 203.91,49.5 203.91,50.88 202.74,50.88 202.74,52.43 203.96,52.43 203.96,53.82 203.66,53.82 203.66,59.33 216.97,59.33 216.97,54.86 229.46,54.86 229.46,44.55 236.91,44.55 236.91,59.11 240.39,59.11 240.39,44.55 256.06,44.55 256.06,22.15 273.43,22.15 273.43,29.74 262.97,29.74 262.97,46.51 261.7,46.51 261.7,54.41 266.65,54.41 266.65,63.5 266.67,63.53 269.24,63.53 ; 3 cut-outs
PGND on TOP: 104.57,59.33 151.21,59.33 151.21,53.19 150.93,53.19 150.93,44.15 127.97,44.15 127.97,44.12 126.49,44.12 126.49,1.35 101.93,1.35 101.93,24.38 104.34,24.38 104.34,48.56 103.66,49.25 102.72,49.25 102.72,50.16 104.39,50.16 104.72,49.83 105.84,49.83 105.84,51.61 105.82,51.64 104.93,51.64 104.78,51.79 104.78,53.04 104.57,53.24
PGND on TOP: 152.76,151.08 202.82,151.08 202.82,128.07 200.71,128.07 200.71,104.93 197.31,104.93 197.31,97.1 199.36,97.1 201.37,99.11 201.37,102.9 202.49,102.9 202.49,101.52 203.66,101.52 203.66,99.97 202.44,99.97 202.44,98.58 202.87,98.58 202.87,93.07 153.59,93.07 153.59,99.21 155.04,99.21 155.91,100.08 155.91,101.9 155.88,101.93 155.88,103.89 154,103.89 154,127.99 152.76,127.99 ; 1 cut-out
PGND on TOP: 51.16,151.08 75.84,151.08 75.84,108.86 98.73,108.86 98.73,103.96 99.54,103.15 100.48,103.15 100.48,102.23 98.81,102.23 98.48,102.57 97.36,102.57 97.36,100.79 97.38,100.76 98.27,100.76 98.42,100.61 98.42,99.36 98.63,99.16 98.63,93.07 51.99,93.07 51.99,99.21 53.44,99.21 54.31,100.08 54.31,101.9 54.28,101.93 54.28,103.89 52.27,103.89 52.27,105.49 52.4,105.61 52.4,127.99 51.16,127.99
PGND on TOP: 53.77,59.33 100.41,59.33 100.41,53.19 100.13,53.19 100.13,44.15 75.69,44.15 75.69,1.35 51.13,1.35 51.13,24.38 53.64,24.38 53.64,48.46 52.86,49.25 51.92,49.25 51.92,50.16 53.59,50.16 53.92,49.83 55.04,49.83 55.04,51.61 55.02,51.64 54.13,51.64 53.98,51.79 53.98,53.04 53.77,53.24
PGND on TOP: 224.54,151.1 278.08,151.1 278.08,116.76 259.33,116.76 259.33,90.65 258.04,90.65 258.04,84.84 224.54,84.84 224.54,96.9 208.74,96.9 208.74,104.32 224.54,104.32 ; 2 cut-outs
PGND on TOP: 155.37,59.33 197.66,59.33 197.66,48.59 177.29,48.59 177.29,1.35 152.73,1.35 152.73,24.38 155.14,24.38 155.14,48.56 154.46,49.25 153.52,49.25 153.52,50.16 155.19,50.16 155.52,49.83 156.64,49.83 156.64,51.61 156.62,51.64 155.73,51.64 155.57,51.79 155.57,53.04 155.37,53.24
PGND on BOTTOM: 1.3,151.1 278.13,151.1 278.13,1.27 1.3,1.27
PGND on L2: 1.3,151.1 1.3,1.32 278.08,1.32 278.08,151.1 ; 8 cut-outs
PGND on L3: 1.27,151.13 278.13,151.13 278.13,1.27 1.27,1.27 ; 1 cut-out
PVIN on TOP (solid shape): 50.27,100.05 49.23,100.05 49.23,100.95 49.93,100.95 49.93,101.4 50.27,101.4
PVIN on TOP (solid shape): 52.37,51.45 51.67,51.45 51.67,51 51.33,51 51.33,52.35 52.37,52.35
PVIN on TOP (solid shape): 101.07,100.05 100.03,100.05 100.03,100.95 100.73,100.95 100.73,101.4 101.07,101.4
PVIN on TOP (solid shape): 103.17,51.45 102.47,51.45 102.47,51 102.13,51 102.13,52.35 103.17,52.35
PVIN on TOP (solid shape): 151.87,100.05 150.83,100.05 150.83,100.95 151.53,100.95 151.53,101.4 151.87,101.4
PVIN on TOP (solid shape): 153.97,51.45 153.27,51.45 153.27,51 152.93,51 152.93,52.35 153.97,52.35
PVIN on BOTTOM (solid shape): 50.24,99.59 51.36,99.59 51.36,95.5 48.46,95.5 48.46,99.26 48.92,99.26 48.92,100.94 50.24,100.94
PVIN on BOTTOM (solid shape): 53.14,53.14 52.68,53.14 52.68,51.46 51.36,51.46 51.36,52.81 50.24,52.81 50.24,56.9 53.14,56.9
PVIN on BOTTOM (solid shape): 101.04,99.59 102.16,99.59 102.16,95.5 99.26,95.5 99.26,99.26 99.72,99.26 99.72,100.94 101.04,100.94
PVIN on BOTTOM (solid shape): 103.94,53.14 103.48,53.14 103.48,51.46 102.16,51.46 102.16,52.81 101.04,52.81 101.04,56.9 103.94,56.9
PVIN on BOTTOM (solid shape): 151.84,100.84 151.84,99.59 152.96,99.59 152.96,95.5 150.06,95.5 150.06,99.26 150.52,99.26 150.52,100.94 151.74,100.94
PVIN on BOTTOM (solid shape): 154.74,53.14 154.28,53.14 154.28,51.46 153.14,51.46 152.96,51.64 152.96,52.81 151.84,52.81 151.84,56.9 154.74,56.9
PVIN on TOP: outline of 130 points within 6.71,45.42 235.71,101.52
PVIN on BOTTOM: 203.38,93.57 203.38,97.64 204.01,97.64 204.01,101.98 206.12,101.98 207.01,101.09 207.01,93.57
PVIN on BOTTOM: 231.8,53.14 236.47,53.14 236.47,51.16 235.28,51.16 235.28,47.29 231.8,47.29
PVIN on BOTTOM: 203.02,58.83 203.02,54.61 202.39,54.61 202.39,50.55 200.15,50.55 199.39,51.31 199.39,58.83
(no net) on TOP: 1.37,151.05 25.02,151.05 25.02,108.86 48.06,108.86 48.06,103.84 48.74,103.15 49.68,103.15 49.68,102.23 48.01,102.23 47.68,102.57 46.56,102.57 46.56,100.79 46.58,100.76 47.47,100.76 47.62,100.61 47.62,99.36 47.83,99.16 47.83,93.07 43.05,93.07 43.05,93.09 25.78,93.09 25.78,97.69 5.99,97.69 5.99,78.84 17.86,78.84 17.86,77.57 27.1,77.57 27.1,60.81 11.05,60.81 11.05,49.45 19.05,49.45 19.05,50.39 36.68,50.39 36.68,59.33 49.58,59.33 49.58,53.19 49.33,53.19 49.33,44.15 25.58,44.15 25.58,1.3 5.23,1.3 5.23,1.32 1.37,1.32
(no net) on TOP: 101.96,151.08 126.64,151.08 126.64,108.86 149.66,108.86 149.66,103.84 150.34,103.15 151.28,103.15 151.28,102.23 149.61,102.23 149.28,102.57 148.16,102.57 148.16,100.79 148.18,100.76 149.07,100.76 149.22,100.61 149.22,99.36 149.43,99.16 149.43,93.12 149.42,93.1 149.43,93.09 149.43,93.07 102.79,93.07 102.79,99.21 104.24,99.21 105.11,100.08 105.11,101.9 105.08,101.93 105.08,103.89 103.2,103.89 103.2,127.99 101.96,127.99
(no net) on TOP: 49.94,49.71 51.66,49.71 51.66,48.79 52.58,48.79 53.01,48.36 53.01,25.1 50.44,25.1 50.44,17.64 47.69,17.64 47.68,17.63 47.68,10.41 50.39,10.41 50.39,1.32 26.87,1.32 26.87,43.46 49.78,43.46 49.78,48.92 49.94,49.07
(no net) on BOTTOM: 100.94,49.71 102.36,49.71 103.84,48.23 103.84,25.1 101.24,25.1 101.24,17.65 97.94,17.65 97.94,10.41 101.19,10.41 101.19,1.32 76.58,1.32 76.58,43.46 100.6,43.46 100.6,48.26 100.61,48.26 100.61,49.38
(no net) on BOTTOM: 151.74,49.71 153.14,49.71 154.64,48.21 154.64,25.1 152.04,25.1 152.04,17.65 148.84,17.65 148.84,10.41 151.99,10.41 151.99,1.32 127.38,1.32 127.38,43.46 151.38,43.46 151.38,49.35
(no net) on BOTTOM: 50.27,100.94 48.92,100.94 48.92,99.26 48.46,99.26 48.46,95.5 51.36,95.5 51.36,99.59 50.24,99.59 50.24,100.91
(no net) on BOTTOM: 101.07,100.94 99.72,100.94 99.72,99.26 99.26,99.26 99.26,95.5 102.16,95.5 102.16,99.59 101.04,99.59 101.04,100.91
(no net) on BOTTOM: 102.13,51.46 103.48,51.46 103.48,53.14 103.94,53.14 103.94,56.9 101.04,56.9 101.04,52.81 102.16,52.81 102.16,51.49
(no net) on BOTTOM: 51.33,51.46 52.68,51.46 52.68,53.14 53.14,53.14 53.14,56.9 50.24,56.9 50.24,52.81 51.36,52.81 51.36,51.49
(no net) on BOTTOM: 153.14,51.46 154.28,51.46 154.28,53.14 154.74,53.14 154.74,56.9 151.84,56.9 151.84,52.81 152.96,52.81 152.96,51.64
(no net) on BOTTOM: 151.74,100.94 150.52,100.94 150.52,99.26 150.06,99.26 150.06,95.5 152.96,95.5 152.96,99.59 151.84,99.59 151.84,100.84
(no net) on L3: 102.41,45.09 102.41,46.84 100.56,46.84 100.56,45.09
(no net) on L3: 100.79,107.31 100.79,105.56 102.64,105.56 102.64,107.31
(no net) on L3: 153.21,45.09 153.21,46.84 151.36,46.84 151.36,45.09
(no net) on L3: 151.59,107.31 151.59,105.56 153.44,105.56 153.44,107.31
(no net) on L3: 51.61,45.09 51.61,46.84 49.76,46.84 49.76,45.09
(no net) on L3: 49.99,107.31 49.99,105.56 51.84,105.56 51.84,107.31
VOUT1 on L3 (solid shape): 51.84,105.56 49.99,105.56 49.99,105.82 49.99,105.84 50.01,105.93 50.02,106.02 50.01,106.11 49.99,106.2 49.99,106.22 49.99,106.71 49.99,106.73 50.01,106.82 50.02,106.91 50.01,107 49.99,107.09 49.99,107.1 49.99,107.31 51.84,107.31
VOUT1 on TOP: 47.37,142.65 47.37,134.9 50.44,134.9 50.44,127.25 51.77,127.25 51.77,103.43 51.66,103.33 51.66,102.69 49.94,102.69 49.94,103.61 49.02,103.61 48.69,103.94 48.69,109.6 25.78,109.6 25.78,151.08 50.44,151.08 50.44,142.65
VOUT1 on BOTTOM: 25.78,151.08 50.44,151.08 50.44,142.65 47.14,142.65 47.14,134.9 50.44,134.9 50.44,127.25 51.79,127.25 51.79,102.79 51.66,102.79 51.66,102.69 50.16,102.69 48.82,104.04 48.69,104.04 48.69,109.6 25.78,109.6
VOUT2 on L3 (solid shape): 102.64,105.56 100.79,105.56 100.79,105.82 100.79,105.84 100.81,105.93 100.82,106.02 100.81,106.11 100.79,106.2 100.79,106.22 100.79,106.71 100.79,106.73 100.81,106.82 100.82,106.91 100.81,107 100.79,107.09 100.79,107.1 100.79,107.31 102.64,107.31
VOUT2 on TOP: 76.58,151.08 101.24,151.08 101.24,142.65 98.17,142.65 98.17,134.9 101.24,134.9 101.24,127.25 102.57,127.25 102.57,103.43 102.46,103.33 102.46,102.69 100.74,102.69 100.74,103.61 99.82,103.61 99.49,103.94 99.49,109.6 76.58,109.6
VOUT2 on BOTTOM: 76.58,151.08 101.24,151.08 101.24,142.65 97.76,142.65 97.76,134.9 101.24,134.9 101.24,127.25 102.59,127.25 102.59,103.02 102.26,102.69 100.97,102.69 99.59,104.06 99.49,104.06 99.49,109.6 76.58,109.6
VOUT3 on L3 (solid shape): 153.44,105.56 151.59,105.56 151.59,105.82 151.59,105.84 151.61,105.93 151.62,106.02 151.61,106.11 151.59,106.2 151.59,106.22 151.59,106.71 151.59,106.73 151.61,106.82 151.62,106.91 151.61,107 151.59,107.09 151.59,107.1 151.59,107.31 153.44,107.31
VOUT3 on TOP: 127.38,151.08 152.04,151.08 152.04,142.65 148.97,142.65 148.97,134.9 152.04,134.9 152.04,127.25 153.37,127.25 153.37,103.43 153.26,103.33 153.26,102.69 151.54,102.69 151.54,103.61 150.62,103.61 150.29,103.94 150.29,109.6 127.38,109.6
VOUT3 on BOTTOM: 127.38,151.08 152.04,151.08 152.04,142.65 148.54,142.65 148.54,134.9 152.04,134.9 152.04,127.25 153.39,127.25 153.39,103 153.09,102.69 151.74,102.69 150.39,104.04 150.32,104.04 150.29,104.06 150.29,109.6 127.38,109.6
VOUT4 on TOP (solid shape): outline of 410 points within 26.87,1.32 53.01,49.71
VOUT4 on L3 (solid shape): 51.61,46.58 51.61,46.56 51.59,46.47 51.58,46.38 51.59,46.29 51.61,46.2 51.61,46.18 51.61,45.69 51.61,45.67 51.59,45.58 51.58,45.49 51.59,45.4 51.61,45.31 51.61,45.3 51.61,45.09 49.76,45.09 49.76,46.84 51.61,46.84
VOUT4 on BOTTOM: 50.14,49.71 51.51,49.71 53.04,48.18 53.04,25.1 50.44,25.1 50.44,17.65 47.04,17.65 47.04,10.41 50.39,10.41 50.39,1.32 26.87,1.32 26.87,43.46 49.8,43.46 49.8,48.26 49.81,48.26 49.81,49.38
VOUT5 on BOTTOM (solid shape): outline of 408 points within 76.58,1.32 103.84,49.71
VOUT5 on L3 (solid shape): 102.41,46.58 102.41,46.56 102.39,46.47 102.38,46.38 102.39,46.29 102.41,46.2 102.41,46.18 102.41,45.69 102.41,45.67 102.39,45.58 102.38,45.49 102.39,45.4 102.41,45.31 102.41,45.3 102.41,45.09 100.56,45.09 100.56,46.84 102.41,46.84
VOUT5 on TOP: 100.74,49.71 102.46,49.71 102.46,48.79 103.38,48.79 103.81,48.36 103.81,25.1 101.24,25.1 101.24,17.64 98.49,17.64 98.48,17.63 98.48,10.41 101.19,10.41 101.19,1.32 76.58,1.32 76.58,43.46 100.58,43.46 100.58,48.92 100.74,49.07
VOUT6 on BOTTOM (solid shape): outline of 406 points within 127.38,1.32 154.64,49.71
VOUT6 on L3 (solid shape): 153.21,46.58 153.21,46.56 153.19,46.47 153.18,46.38 153.19,46.29 153.21,46.2 153.21,46.18 153.21,45.69 153.21,45.67 153.19,45.58 153.18,45.49 153.19,45.4 153.21,45.31 153.21,45.3 153.21,45.09 151.36,45.09 151.36,46.84 153.21,46.84
VOUT6 on TOP: 151.54,49.71 153.26,49.71 153.26,48.79 154.18,48.79 154.61,48.36 154.61,25.1 152.04,25.1 152.04,17.64 149.29,17.64 149.28,17.63 149.28,10.41 151.99,10.41 151.99,1.32 127.38,1.32 127.38,43.46 151.38,43.46 151.38,48.92 151.54,49.07
VOUT7 on TOP: 223.77,105.18 205.94,105.18 205.94,104.7 205.05,104.7 205.05,103.2 201.37,103.2 201.37,111.23 201.4,111.23 201.4,127.28 203.58,127.28 203.58,134.34 206.63,134.34 206.63,143.21 203.56,143.21 203.56,151.08 223.77,151.08
VOUT7 on BOTTOM: 203.56,151.08 223.77,151.08 223.77,105.18 206.45,105.18 205.13,103.86 205.13,103.45 204.88,103.2 201.37,103.2 201.37,127.28 203.58,127.28 203.58,134.34 206.86,134.34 206.86,143.21 203.56,143.21
VOUT8 on TOP: 201.35,49.2 205.03,49.2 205.03,25.07 202.82,25.07 202.82,18.03 199.67,18.03 199.67,10.34 202.87,10.34 202.87,1.32 178.18,1.32 178.18,41.12 178.21,41.12 178.21,47.7 201.35,47.7
VOUT8 on BOTTOM: 201.24,49.2 205.03,49.2 205.03,25.07 202.82,25.07 202.82,18.03 199.67,18.03 199.67,10.34 202.87,10.34 202.87,1.32 178.18,1.32 178.18,41.12 178.21,41.12 178.21,47.7 200.43,47.7 201.27,48.54 201.27,49.17
N983153 on BOTTOM: 202.72,99.69 202.67,99.64 202.67,98.91 201.14,98.91 201.14,97.92 203.66,97.92 203.66,99.69
N983255 on TOP: 197.92,97.71 199.31,97.71 200.89,99.29 200.89,99.62 198.68,99.62 197.92,98.86
N983255 on BOTTOM: 200.51,97.92 200.51,99.44 198.25,99.44 198.25,97.92
N1133327 on BOTTOM: 203.68,52.7 203.73,52.76 203.73,53.49 205.26,53.49 205.26,54.48 202.74,54.48 202.74,52.7
N1133411 on TOP: 208.48,54.69 207.09,54.69 205.51,53.11 205.51,52.78 207.72,52.78 208.48,53.54
N1133411 on BOTTOM: 205.89,54.48 205.89,52.96 208.1,52.96 208.1,54.48

Small or netless copper shapes (teardrops, artwork), in the pictures only: 1 on TOP

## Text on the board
User.Comments: CR_1_4 | CR_1_5 | CR_1_2 | CR_1_6 | CR_1_3 | CR_2_1 | .75:1 | 1:1
Ref Des/Silkscreen Top: 8mm | 8.9mm | SALERT | SYNC | 13.5mm | 16.6mm | EN1 | EN2 | EN3 | EN4 | EN5 | EN6 | EN7 | EN8 | GND | SDA | SCL | 3.3V | PVIN | PGND | VOUT4 | VOUT1 | VOUT5 | VOUT2 | VOUT6 | VOUT3 | VOUT8 | VOUT7 | S/N | POWER MICRO BOARD REV | uPOL
L2: GROUND PLANE
L3: INTERNAL SIGNAL | 3
DIMENSION: FARADAY SEMI | 17 | 18
User.9: SOLDER SIDE SILKSCREEN | COMP SN60. | 17. ALL 0.008 AND 0.010 VIA DRILLS (EXCEPT AS NOTED IN NOTE 18) | SHALL BE PLUGGED WITH LPI SOLDERMASK PRIOR TO APPLYING | THE COMPONENT AND SOLDER SIDE SOLDER MASKS. | 18. INDICATED VIAS SHALL BE COPPER FILLED.
User.11: SLOT 0.118X0.039 | SLOT 0.039X0.118 | SLOT 0.039X0.138 | FIGURE | SIZE | 0.008 | 0.010 | 0.040 | 0.073 | 0.087 | 0.094 | 0.130 | DRILL CHART | ALL UNITS ARE IN INCHES | TOLERANCE | +0.003/-0.008 | +0.003/-0.010 | +0.003/-0.003 | PLATED | NON-PLATED | QTY | 308 | 493 | 1 | 53 | 78 | 4
User.13: PG8 | PG7 | PG6 | PG5 | PG4 | PG3 | PG2 | PG1 | R63 | R62 | R61 | R60 | R59 | R58 | R57 | R56 | J18 | T1 | T2 | J1 | T9 | T3 | R12 | C3 | U4 | C4 | C1 | C20 | C23 | C106 | J2 | C102 | J5 | C2 | C5 | C22 | U1 | C19 | R3 | C21 | T14 | T4 | T11 | T5 | R23 | C9 | U5 | C10 | C8 | C33 | C26 | J6 | C103 | C105 | J3 | C7 | C11 | C31 | C25 | U2 | R6 | C29 | T10 | T6 | T7 | T13 | C15 | R24 | U6 | C16 | C14 | C27 | C34 | C107 | J4 | C104 | J7 | C17 | C13 | C32 | C28 | U3 | R9 | C30 | T8 | T12 | J17 | 3 | 1 | C115 | C116 | T17 | T18 | R39 | C117 | U7 | R45 | C38 | C39 | J9 | C108 | J8 | C109 | C49 | C48 | C47 | R27 | U8 | C111 | C110 | C118 | C119 | C120 | C44 | C45 | R51 | T16 | T15 | C43 | J14 | U11 | R74 | R18 | R55 | R75 | R73 | R72 | R71 | R70 | R69 | R68 | R67 | R66 | SW3 | SW2 | SW1 | J19 | J20 | J21 | J11 | 19 | 2 | 4 | 5 | 6 | 7 | 8 | 20 | ON | J13 | R76 | R77 | R78 | R47 | R48 | C151 | C126 | C131 | U9 | C125 | R46 | R38 | R42 | C51 | C124 | C122 | C123 | C114 | R36 | C40 | C41 | R44 | R53 | C113 | C112 | C42 | R50 | C53 | C52 | C50 | R52 | C121 | R54 | R31 | C149 | C144 | R22 | C136 | C150 | C143 | R7 | C133 | C148 | C141 | R21 | C137 | C147 | C142 | R4 | C132 | C146 | C139 | R10 | C135 | C145 | C140 | R1 | C134 | D15 | V1 | C101 | C138 | C128 | C129 | R65 | U10 | R64 | C130 | S/N | POWER MICRO BOARD REV | uPOL | ASSEMBLY TOP VIEW | ASSEMBLY BOTTOM VIEW
